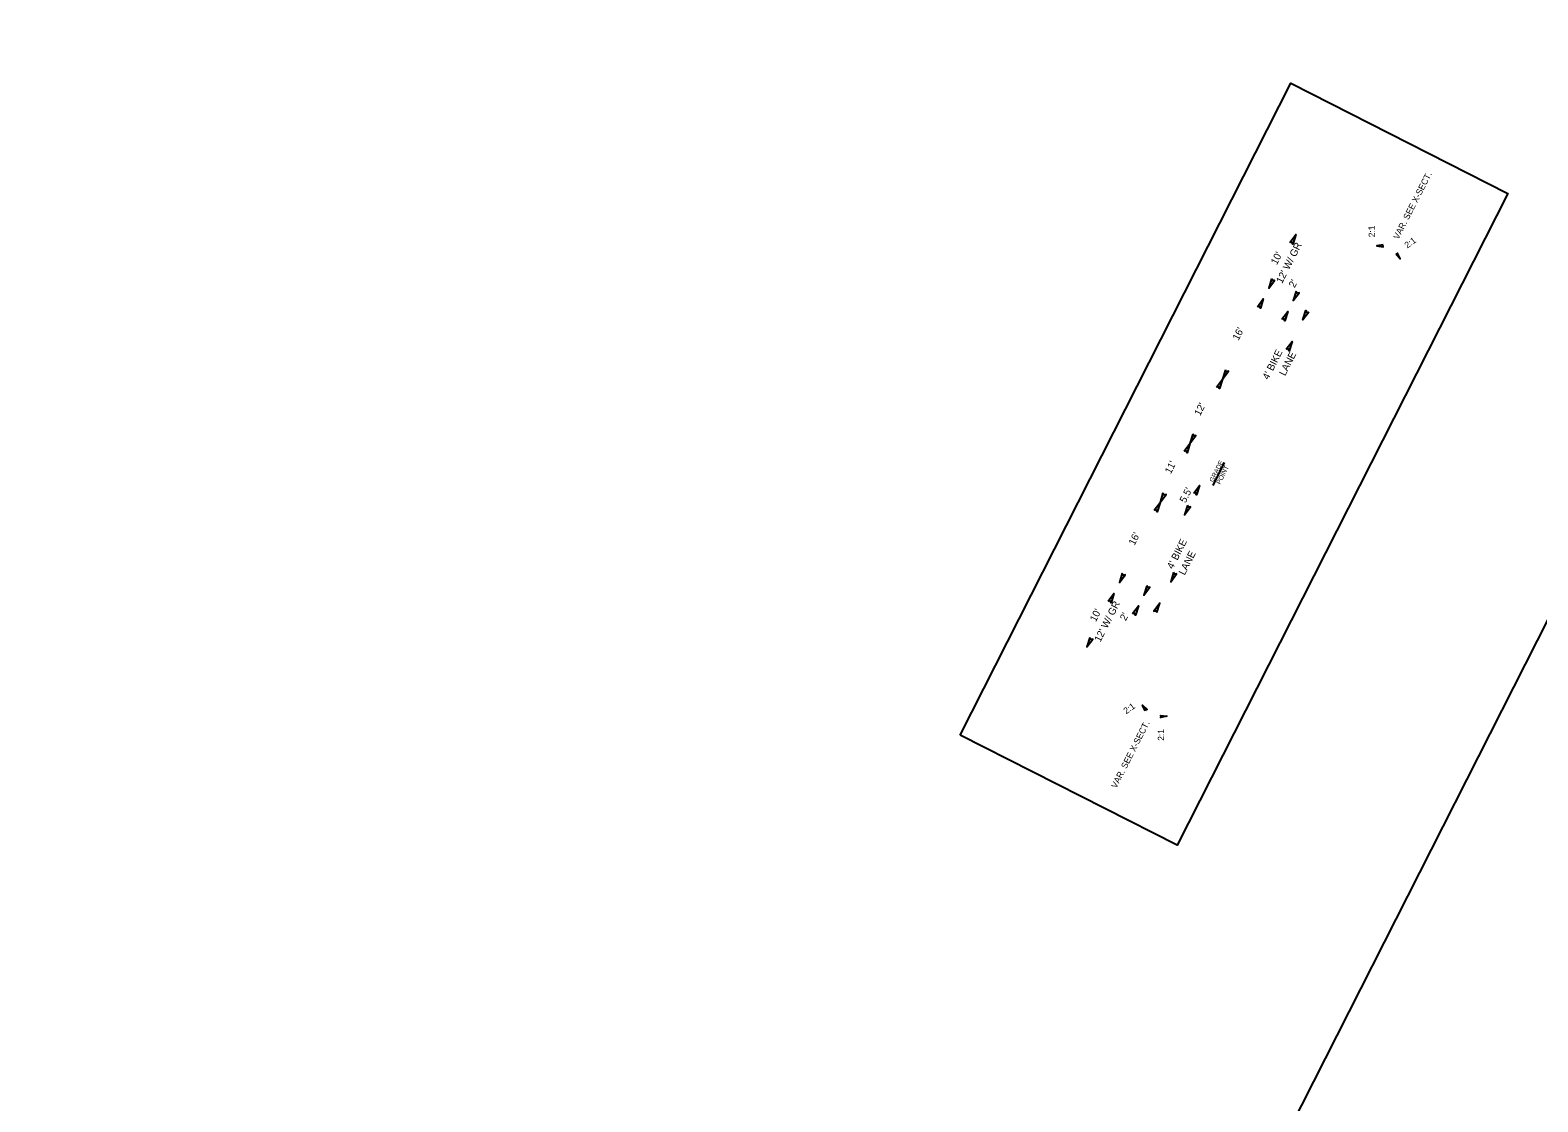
# Model space of a CAD drawing. Extents: x 1974386 to 1979988, y 776712 to 784860.
# Drawn here: x 1974386 to 1975893, y 780223 to 781294 of the extents above; entities that cross this region are included whole.
import ezdxf

# ---------------------------------------------------------------- set-up
doc = ezdxf.new("R2010")
doc.units = 0
for name, color, linetype in [('Default', 7, 'Continuous'), ('Old_Level_11', 7, 'Continuous'), ('Old_Level_3', 7, 'Continuous'), ('Old_Level_4', 7, 'Continuous')]:
    doc.layers.add(name, color=color, linetype=linetype)

msp = doc.modelspace()

# ---------------------------------------------------------------- linework, layer by layer
at = {"layer": 'Default'}
msp.add_lwpolyline([(1978010, 784859.9), (1974385.9, 777715.1), (1976364, 776711.7), (1979988.1, 783856.5)], close=True, dxfattribs=at)
at = {"layer": 'Old_Level_11'}
for points in [[(1975645, 781082.2), (1975650.8, 781090), (1975648, 781080.6), (1975647, 781082.5)], [(1975738.2, 781079.9), (1975731.9, 781078.9), (1975738.2, 781077.7), (1975737.4, 781078.8)], [(1975750.7, 781070.4), (1975755, 781065.7), (1975752.6, 781071.6), (1975752, 781070.3)], [(1975626.6, 781045.8), (1975623.7, 781036.5), (1975629.6, 781044.3), (1975627.5, 781044)], [(1975612.4, 781017.9), (1975618.3, 781025.8), (1975615.4, 781016.4), (1975614.4, 781018.2)], [(1975651.1, 781033.4), (1975648.2, 781024), (1975654.1, 781031.9), (1975652, 781031.6)], [(1975637, 781005.5), (1975642.8, 781013.3), (1975639.9, 781003.9), (1975639, 781005.8)], [(1975663.8, 781012.6), (1975658, 781004.7), (1975660.8, 781014.1), (1975661.8, 781012.3)], [(1975641.3, 780975.5), (1975647.1, 780983.3), (1975644.3, 780973.9), (1975643.3, 780975.8)], [(1975580.4, 780954.8), (1975577.6, 780945.5), (1975583.5, 780953.4), (1975581.4, 780953)], [(1975571.7, 780937.7), (1975577.6, 780945.5), (1975574.7, 780936.1), (1975573.7, 780938)], [(1975547.9, 780890.6), (1975545, 780881.3), (1975550.9, 780889.1), (1975548.8, 780888.8)], [(1975539.2, 780873.5), (1975545, 780881.3), (1975542.2, 780871.9), (1975541.2, 780873.8)], [(1975518, 780831.8), (1975515.2, 780822.4), (1975521.1, 780830.3), (1975519, 780830)], [(1975548.8, 780831.6), (1975554.6, 780839.4), (1975551.7, 780830), (1975550.8, 780831.9)], [(1975509.3, 780814.6), (1975515.2, 780822.4), (1975512.3, 780813), (1975511.3, 780814.9)], [(1975542.5, 780819.3), (1975539.7, 780810), (1975545.6, 780817.8), (1975543.5, 780817.5)], [(1975477.3, 780751.5), (1975474.5, 780742.2), (1975480.4, 780750), (1975478.3, 780749.7)], [(1975528.6, 780752.4), (1975525.8, 780743), (1975531.7, 780750.9), (1975529.6, 780750.6)], [(1975463.2, 780723.6), (1975469, 780731.5), (1975466.2, 780722), (1975465.2, 780723.9)], [(1975501.8, 780739.1), (1975499, 780729.7), (1975504.9, 780737.6), (1975502.8, 780737.3)], [(1975487.7, 780711.2), (1975493.5, 780719), (1975490.7, 780709.6), (1975489.7, 780711.5)], [(1975512, 780712.3), (1975514.9, 780721.6), (1975509, 780713.8), (1975511.1, 780714.1)], [(1975444.8, 780687.3), (1975441.9, 780677.9), (1975447.8, 780685.8), (1975445.7, 780685.5)], [(1975500.4, 780614.1), (1975497.5, 780619.7), (1975502.2, 780615.4), (1975500.8, 780615.3)], [(1975515.4, 780609.5), (1975521.8, 780608.9), (1975515.6, 780607.3), (1975516.3, 780608.5)]]:
    msp.add_lwpolyline(points, close=True, dxfattribs=at)
at = {"layer": 'Old_Level_3'}
msp.add_line((1975568.1, 780839.4), (1975579.7, 780862.2), dxfattribs=at)
at = {"layer": 'Old_Level_4'}
msp.add_lwpolyline([(1975315.3, 780589.8), (1975645.7, 781241.2), (1975862.6, 781131.1), (1975532.2, 780479.7)], close=True, dxfattribs=at)

# ---------------------------------------------------------------- texts
at = {"layer": 'Old_Level_11'}
for s, height, rotation, p in [('VAR. SEE X-SECT.', 6.276, 63.1118, (1975753.5, 781084.7)), ('2:1', 6.28, 91.322, (1975729.9, 781087.4)), ('2:1', 6.28, 36.1111, (1975762.3, 781076)), ("10'", 7.2, 63.1118, (1975631.8, 781059.3)), ("12' W/ GR", 7.2, 63.1118, (1975637.1, 781040.6)), ("2'", 7.2, 63.1118, (1975649.7, 781036.3)), ("16'", 7.2, 63.1118, (1975593.5, 780983.7)), ("4' BIKE ", 7.2, 63.1118, (1975623.4, 780944.4)), ('LANE', 7.2, 63.1118, (1975640.1, 780948.2)), ("12'", 7.2, 63.1118, (1975555.2, 780908.3)), ("11'", 7.2, 63.1118, (1975525.8, 780850.3)), ('GRADE', 4.71, 63.1118, (1975568.3, 780842.2)), ('POINT', 4.71, 63.1118, (1975575.2, 780840)), ("5.5'", 7.2, 63.1118, (1975540.6, 780821.3)), ("16'", 7.2, 63.1118, (1975489.6, 780778.9)), ("4' BIKE ", 7.2, 63.1118, (1975527.9, 780755.1)), ('LANE', 7.2, 63.1118, (1975539.7, 780749.1)), ("10'", 7.2, 63.1118, (1975450.9, 780702.5)), ("12' W/ GR", 7.2, 63.1118, (1975455.4, 780682.2)), ("2'", 7.2, 63.1118, (1975480.9, 780703.5)), ('2:1', 6.28, 34.9016, (1975481.3, 780610.6)), ('VAR. SEE X-SECT.', 6.276, 63.1118, (1975471.5, 780536.1)), ('2:1', 6.28, 90.1125, (1975519.2, 780584.2))]:
    msp.add_text(s, height=height, rotation=rotation, dxfattribs=at).set_placement(p)

doc.saveas('drawing.dxf')
